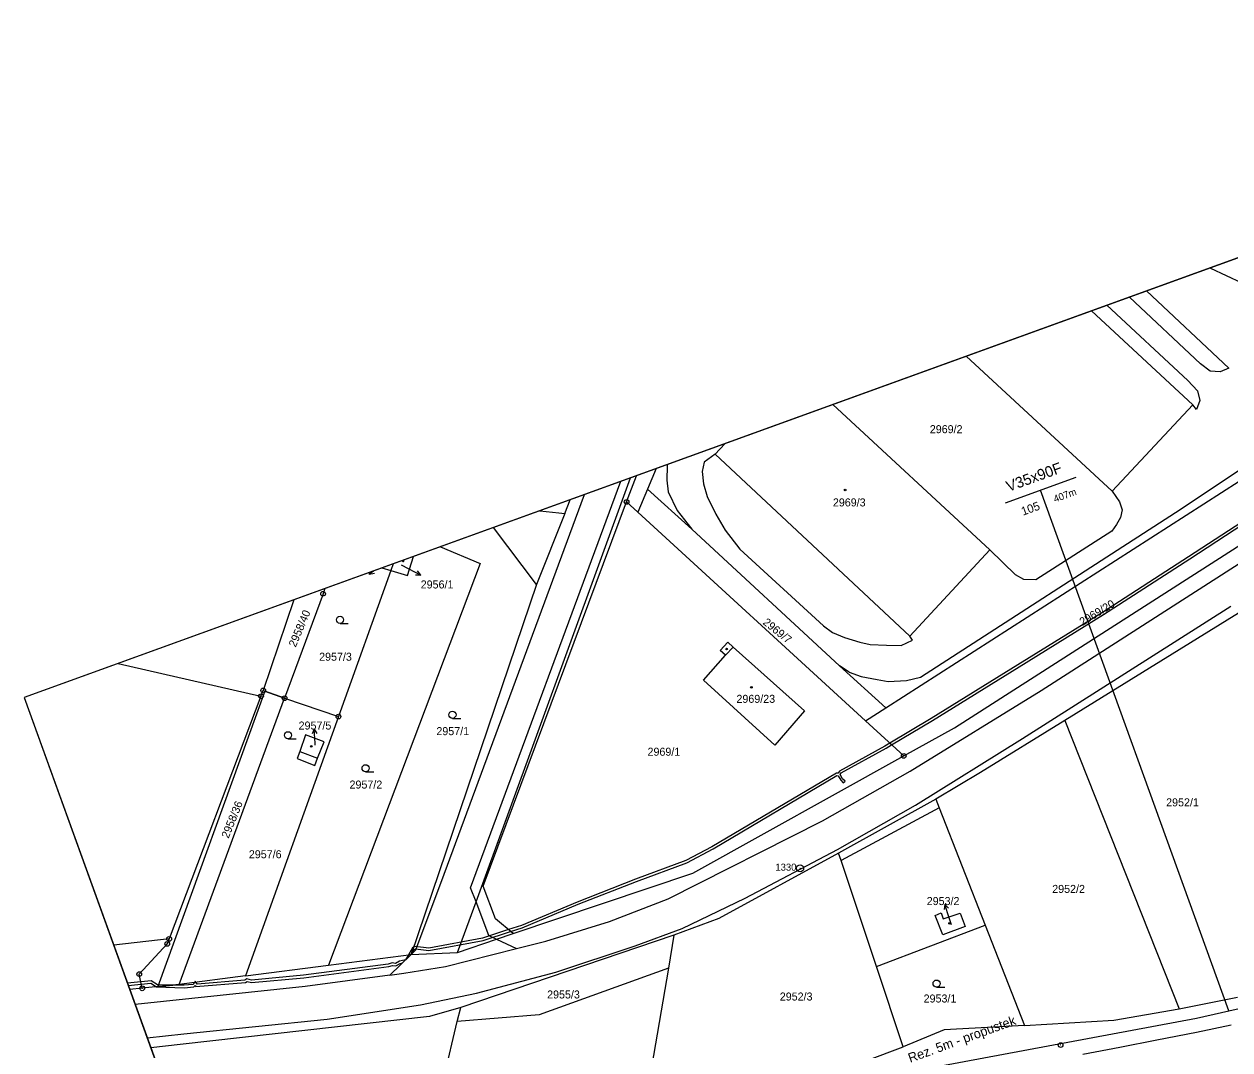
# Model space of a CAD drawing. Extents: x -620552 to -620056, y -1123312 to -1122890.
# Drawn here: x -620552.1 to -620295.9, y -1123107.4 to -1122889.6 of the extents above; entities that cross this region are included whole.
import ezdxf

# ---------------------------------------------------------------- set-up
doc = ezdxf.new("R2010")
doc.units = 0
for name, color, linetype in [('HranDP', 7, 'Continuous'), ('Hranice parcel', 7, 'Continuous'), ('Parcelní čísla', 7, 'Continuous'), ('Pop  PČ popisy', 7, 'Continuous'), ('Rámečky', 7, 'Continuous'), ('Rámečky-tisk', 7, 'Continuous'), ('Vnitřní kresba', 7, 'Continuous'), ('Vrstva 1', 7, 'Continuous'), ('Vrstva 3', 7, 'Continuous'), ('Vrstva 33', 7, 'Continuous'), ('Vrstva 7', 7, 'Continuous'), ('Věcná břemena k části', 7, 'Continuous'), ('Značky bodu BP', 7, 'Continuous'), ('Značky budov', 7, 'Continuous'), ('Značky kultur', 7, 'Continuous')]:
    doc.layers.add(name, color=color, linetype=linetype)

msp = doc.modelspace()

# ---------------------------------------------------------------- linework, layer by layer
at = {"layer": 'HranDP'}
msp.add_line((-620306.69, -1123098.69), (-620294.3, -1123096.22), dxfattribs=at)
for points in [[(-620339.56, -1123102.2), (-620320.55, -1123101.1), (-620306.69, -1123098.69)], [(-620339.56, -1123102.2), (-620356.6, -1123103.13), (-620365.33, -1123106.73)], [(-620420.55, -1123121.3), (-620381.33, -1123112.8), (-620365.33, -1123106.73)]]:
    msp.add_lwpolyline(points, dxfattribs=at)
at = {"layer": 'Hranice parcel'}
for p, q in [((-620369, -1123034.76), (-620282.4, -1122979.23)), ((-620419.67, -1122988.35), (-620421.73, -1122993.23)), ((-620437.23, -1122993.52), (-620436.06, -1122990.58)), ((-620421.73, -1122993.23), (-620424.09, -1122991.06)), ((-620437.23, -1122993.52), (-620443.21, -1123008.56)), ((-620373.35, -1123037.54), (-620421.73, -1122993.23)), ((-620470.61, -1123006.71), (-620469.37, -1123002.64)), ((-620474.2, -1123005.64), (-620485.32, -1123036.63)), ((-620473.68, -1123004.21), (-620474.2, -1123005.64)), ((-620474.2, -1123005.64), (-620470.61, -1123006.71)), ((-620443.21, -1123008.56), (-620469.88, -1123087.14)), ((-620488.59, -1123010.56), (-620496.76, -1123032.74)), ((-620488.18, -1123009.46), (-620488.59, -1123010.56)), ((-620289.02, -1123011.5), (-620330.98, -1123037.45)), ((-620494.8, -1123011.85), (-620501.3, -1123031.09)), ((-620501.77, -1123032.32), (-620501.3, -1123031.09)), ((-620501.77, -1123032.32), (-620521.28, -1123083.84)), ((-620519.15, -1123093.5), (-620496.76, -1123032.74)), ((-620496.76, -1123032.74), (-620485.32, -1123036.63)), ((-620485.32, -1123036.63), (-620505.08, -1123091.68)), ((-620373.35, -1123037.54), (-620369, -1123034.76)), ((-620365.22, -1123044.99), (-620373.35, -1123037.54)), ((-620330.98, -1123037.45), (-620306.69, -1123098.69)), ((-620358.43, -1123054.16), (-620379.05, -1123065.63)), ((-620414.05, -1123083.02), (-620459.28, -1123098.4)), ((-620414.05, -1123083.02), (-620415.21, -1123090.05)), ((-620487.43, -1123089.4), (-620469.88, -1123087.14)), ((-620505.08, -1123091.68), (-620487.43, -1123089.4)), ((-620415.21, -1123090.05), (-620420.55, -1123121.3)), ((-620519.15, -1123093.5), (-620527.01, -1123094.34)), ((-620505.08, -1123091.68), (-620519.15, -1123093.5)), ((-620460.08, -1123101.38), (-620459.28, -1123098.4)), ((-620306.69, -1123098.69), (-620294.3, -1123096.22)), ((-620466.92, -1123130.28), (-620460.08, -1123101.38))]:
    msp.add_line(p, q, dxfattribs=at)
for points in [[(-620325.34, -1122950.49), (-620303.81, -1122970.47), (-620320.91, -1122988.8), (-620351.92, -1122960.11)], [(-620380.28, -1122970.38), (-620346.89, -1123001.2)], [(-620346.89, -1123001.2), (-620363.9, -1123019.53), (-620405.31, -1122980.94), (-620403.21, -1122978.69)], [(-620424.09, -1122991.06), (-620422.01, -1122985.49)], [(-620417.81, -1122983.97), (-620419.67, -1122988.35)], [(-620419.67, -1122988.35), (-620410.26, -1122996.87), (-620378.87, -1123025.88), (-620369, -1123034.76)], [(-620448.18, -1123082.73), (-620451.92, -1123079.58), (-620454.55, -1123072.66), (-620424.09, -1122991.06)], [(-620442.54, -1122992.93), (-620438.47, -1122993.38), (-620437.23, -1122993.52)], [(-620365.22, -1123044.99), (-620354.45, -1123039), (-620287.33, -1122996.04)], [(-620443.21, -1123008.56), (-620452.34, -1122996.48)], [(-620463.61, -1123000.56), (-620455.23, -1123004.12), (-620487.43, -1123089.4)], [(-620476.09, -1123005.08), (-620474.2, -1123005.64)], [(-620402.6, -1123020.87), (-620401.48, -1123021.87), (-620386.27, -1123035.43), (-620392.63, -1123042.68), (-620407.79, -1123028.9), (-620403.06, -1123023.63), (-620404.19, -1123022.62), (-620402.6, -1123020.87)], [(-620532.11, -1123025.36), (-620501.77, -1123032.32)], [(-620501.3, -1123031.09), (-620500.99, -1123031.21), (-620496.76, -1123032.74)], [(-620330.98, -1123037.45), (-620348.88, -1123048.53), (-620358.43, -1123054.16)], [(-620488.38, -1123042.02), (-620492.3, -1123040.51), (-620493.55, -1123044.02), (-620494.11, -1123045.54), (-620490.35, -1123047.05), (-620489.79, -1123045.46), (-620488.38, -1123042.02)], [(-620448.18, -1123082.73), (-620410.01, -1123069.89), (-620365.22, -1123044.99)], [(-620358.43, -1123054.16), (-620357.7, -1123056.02), (-620347.91, -1123080.94), (-620339.56, -1123102.2)], [(-620379.05, -1123065.63), (-620404.47, -1123079.48), (-620414.05, -1123083.02)], [(-620365.33, -1123106.73), (-620371.02, -1123089.67), (-620378.51, -1123067.23), (-620379.05, -1123065.63)], [(-620353.21, -1123078.36), (-620352.17, -1123081.18), (-620356.92, -1123082.98), (-620358.53, -1123078.86), (-620357.25, -1123078.34), (-620356.83, -1123079.58), (-620353.21, -1123078.36)], [(-620469.88, -1123087.14), (-620460.03, -1123086.72), (-620451.71, -1123083.91), (-620448.18, -1123082.73)], [(-620521.28, -1123083.84), (-620533.07, -1123085.14)], [(-620527.01, -1123094.34), (-620527.63, -1123091.32), (-620521.69, -1123084.92), (-620521.28, -1123083.84)], [(-620469.88, -1123087.14), (-620474.39, -1123091.54), (-620492.38, -1123093.94), (-620528.51, -1123097.74)], [(-620415.21, -1123090.05), (-620442.66, -1123100), (-620460.08, -1123101.38)], [(-620527.01, -1123094.34), (-620529.64, -1123094.62)], [(-620459.28, -1123098.4), (-620466, -1123100.3), (-620518.97, -1123106.26), (-620525.17, -1123106.96)], [(-620339.56, -1123102.2), (-620320.55, -1123101.1), (-620306.69, -1123098.69)], [(-620339.56, -1123102.2), (-620356.6, -1123103.13), (-620365.33, -1123106.73)], [(-620420.55, -1123121.3), (-620381.33, -1123112.8), (-620365.33, -1123106.73)]]:
    msp.add_lwpolyline(points, dxfattribs=at)
at = {"layer": 'Pop  PČ popisy'}
for p, q in [((-620477.9, -1123005.73), (-620478.77, -1123006.39)), ((-620478.77, -1123006.39), (-620478.56, -1123005.97)), ((-620478.77, -1123006.39), (-620477.67, -1123006.18)), ((-620472, -1123004.4), (-620470.49, -1123005.2)), ((-620470.49, -1123005.2), (-620467.84, -1123006.61)), ((-620467.84, -1123006.61), (-620468.49, -1123005.7)), ((-620467.84, -1123006.61), (-620468.96, -1123006.58)), ((-620490.44, -1123039.28), (-620490.89, -1123040.31)), ((-620490.28, -1123042.28), (-620490.44, -1123039.28)), ((-620490.44, -1123039.28), (-620489.89, -1123040.26)), ((-620490.26, -1123042.74), (-620490.28, -1123042.28)), ((-620356.5, -1123076.52), (-620356.66, -1123077.62)), ((-620355.57, -1123079.37), (-620356.5, -1123076.52)), ((-620356.5, -1123076.52), (-620355.71, -1123077.31)), ((-620355.09, -1123080.85), (-620355.57, -1123079.37))]:
    msp.add_line(p, q, dxfattribs=at)
at = {"layer": 'Rámečky'}
msp.add_line((-620157.19, -1122889.6), (-620552.1, -1123032.6), dxfattribs=at)
msp.add_lwpolyline([(-620552.1, -1123032.6), (-620450.98, -1123311.85), (-620056.07, -1123168.86)], dxfattribs=at)
at = {"layer": 'Rámečky-tisk'}
msp.add_line((-620552.1, -1123032.6), (-620450.98, -1123311.85), dxfattribs=at)
msp.add_lwpolyline([(-620450.98, -1123311.85), (-620056.07, -1123168.86), (-620157.19, -1122889.6), (-620552.1, -1123032.6)], dxfattribs=at)
at = {"layer": 'Vnitřní kresba'}
for p, q in [((-620300.09, -1122941.34), (-620300.01, -1122941.39)), ((-620300.01, -1122941.39), (-620293.37, -1122944.55)), ((-620313.63, -1122946.25), (-620296.17, -1122962.67)), ((-620322.07, -1122949.31), (-620304.85, -1122965.25)), ((-620302.2, -1122961.76), (-620317.24, -1122947.56)), ((-620300.14, -1122963.26), (-620302.2, -1122961.76)), ((-620296.17, -1122962.67), (-620297.96, -1122963.41)), ((-620304.85, -1122965.25), (-620302.84, -1122967.46)), ((-620297.96, -1122963.41), (-620300.14, -1122963.26)), ((-620302.84, -1122967.46), (-620302.33, -1122969.49)), ((-620303.05, -1122971.44), (-620303.81, -1122970.47)), ((-620302.33, -1122969.49), (-620303.05, -1122971.44)), ((-620415.51, -1122983.37), (-620415.58, -1122986.43)), ((-620415.44, -1122983.11), (-620415.51, -1122983.37)), ((-620407.63, -1122982.63), (-620408.01, -1122984.62)), ((-620405.31, -1122980.94), (-620407.63, -1122982.63)), ((-620307.51, -1122993.27), (-620292.44, -1122983.33)), ((-620456.08, -1123075.99), (-620423.24, -1122985.94)), ((-620408.01, -1122984.62), (-620407.79, -1122987.2)), ((-620457.23, -1123072.97), (-620425.29, -1122986.68)), ((-620415.58, -1122986.43), (-620415.3, -1122988.94)), ((-620407.79, -1122987.2), (-620406.97, -1122989.87)), ((-620462.82, -1123070.13), (-620433.05, -1122989.49)), ((-620415.3, -1122988.94), (-620413.36, -1122992.91)), ((-620406.97, -1122989.87), (-620405.11, -1122993.68)), ((-620320.91, -1122988.8), (-620319.39, -1122991.07)), ((-620319.39, -1122991.07), (-620318.78, -1122992.75)), ((-620413.36, -1122992.91), (-620410.26, -1122996.87)), ((-620361.67, -1123028.28), (-620307.51, -1122993.27)), ((-620318.78, -1122992.75), (-620319.15, -1122994.37)), ((-620405.11, -1122993.68), (-620403.13, -1122997.02)), ((-620319.98, -1122995.84), (-620320.99, -1122997.25)), ((-620319.15, -1122994.37), (-620319.98, -1122995.84)), ((-620403.13, -1122997.02), (-620400.01, -1123001.09)), ((-620320.99, -1122997.25), (-620337.13, -1123007.62)), ((-620400.01, -1123001.09), (-620382.25, -1123017.34)), ((-620341.49, -1123006.57), (-620346.89, -1123001.2)), ((-620336.04, -1123031.13), (-620285.65, -1122998.79)), ((-620339.7, -1123007.56), (-620341.49, -1123006.57)), ((-620337.13, -1123007.62), (-620339.7, -1123007.56)), ((-620339.98, -1123041.29), (-620295.72, -1123013.16)), ((-620382.25, -1123017.34), (-620380.35, -1123018.75)), ((-620380.35, -1123018.75), (-620377.77, -1123019.86)), ((-620377.77, -1123019.86), (-620374.53, -1123020.83)), ((-620374.53, -1123020.83), (-620372.37, -1123021.35)), ((-620372.37, -1123021.35), (-620368.87, -1123021.48)), ((-620368.87, -1123021.48), (-620365.77, -1123021.56)), ((-620365.77, -1123021.56), (-620363.32, -1123020.4)), ((-620363.32, -1123020.4), (-620363.9, -1123019.53)), ((-620403.06, -1123023.63), (-620401.48, -1123021.87)), ((-620376.83, -1123027.23), (-620378.87, -1123025.88)), ((-620376.83, -1123027.23), (-620374.25, -1123028.1)), ((-620374.25, -1123028.1), (-620370.88, -1123028.79)), ((-620370.88, -1123028.79), (-620368.56, -1123029.21)), ((-620368.56, -1123029.21), (-620364.63, -1123029)), ((-620364.63, -1123029), (-620361.67, -1123028.28)), ((-620363.85, -1123048.22), (-620336.04, -1123031.13)), ((-620362.71, -1123055.46), (-620339.98, -1123041.29)), ((-620493.55, -1123044.02), (-620489.79, -1123045.46)), ((-620382.46, -1123058.76), (-620363.85, -1123048.22)), ((-620379.28, -1123064.86), (-620362.71, -1123055.46)), ((-620357.7, -1123056.02), (-620378.51, -1123067.23)), ((-620415.29, -1123075.34), (-620382.46, -1123058.76)), ((-620398.9, -1123075.2), (-620379.28, -1123064.86)), ((-620468.85, -1123086.16), (-620462.82, -1123070.13)), ((-620456.08, -1123075.99), (-620457.23, -1123072.97)), ((-620427.73, -1123080.16), (-620415.29, -1123075.34)), ((-620412.3, -1123081.62), (-620398.9, -1123075.2)), ((-620460.03, -1123086.72), (-620456.08, -1123075.99)), ((-620453.39, -1123083.13), (-620456.08, -1123075.99)), ((-620441.26, -1123084.35), (-620427.73, -1123080.16)), ((-620453.39, -1123083.13), (-620451.71, -1123083.91)), ((-620422.27, -1123085.3), (-620412.3, -1123081.62)), ((-620371.02, -1123089.67), (-620347.91, -1123080.94)), ((-620451.71, -1123083.91), (-620447.48, -1123085.9)), ((-620447.48, -1123085.9), (-620441.26, -1123084.35)), ((-620439.16, -1123090.89), (-620422.27, -1123085.3)), ((-620469.88, -1123087.14), (-620468.85, -1123086.16)), ((-620462.59, -1123089.69), (-620447.48, -1123085.9)), ((-620471.42, -1123091.14), (-620462.59, -1123089.69)), ((-620455.99, -1123095.39), (-620439.16, -1123090.89)), ((-620474.39, -1123091.54), (-620471.42, -1123091.14)), ((-620467.87, -1123097.88), (-620455.99, -1123095.39)), ((-620487.74, -1123100.91), (-620467.87, -1123097.88)), ((-620518.16, -1123103.97), (-620487.74, -1123100.91)), ((-620525.94, -1123104.83), (-620518.16, -1123103.97))]:
    msp.add_line(p, q, dxfattribs=at)
at = {"layer": 'Vrstva 1'}
for points in [[(-620490.54, -1123135.38), (-620469.22, -1123131.24), (-620467.69, -1123132.26), (-620387.47, -1123116.43), (-620372.49, -1123113.59), (-620361.88, -1123111.62), (-620302.99, -1123100.7), (-620292.4, -1123098.24)], [(-620295.67, -1123102.19), (-620303.02, -1123103.7), (-620311.43, -1123105.36), (-620319.33, -1123106.87), (-620327.2, -1123108.39)]]:
    msp.add_lwpolyline(points, dxfattribs=at)
at = {"layer": 'Vrstva 33'}
for p, q in [((-620328.63, -1122985.87), (-620343.67, -1122991.32)), ((-620296.13, -1123099.11), (-620336.15, -1122988.59))]:
    msp.add_line(p, q, dxfattribs=at)
at = {"layer": 'Vrstva 7'}
msp.add_line((-620331.84, -1123106.38), (-620331.94, -1123106.4), dxfattribs=at)
msp.add_circle((-620331.89, -1123106.39), 0.5, dxfattribs=at)
at = {"layer": 'Věcná břemena k části'}
msp.add_line((-620530.14, -1123093.23), (-620529.96, -1123093.72), dxfattribs=at)
for points in [[(-620359.12, -1123037.46), (-620340.69, -1123026.08), (-620322.75, -1123014.93), (-620304.43, -1123003.11), (-620287.42, -1122992.06), (-620285.83, -1122990.94), (-620285.6, -1122990.17), (-620287.7, -1122991.64), (-620304.71, -1123002.69), (-620323.01, -1123014.51), (-620340.95, -1123025.66), (-620359.38, -1123037.04), (-620368.18, -1123042.28), (-620367.79, -1123042.63)], [(-620519.15, -1123093.5), (-620496.76, -1123032.74), (-620500.99, -1123031.21), (-620523.67, -1123093.98)], [(-620449.19, -1123081.88), (-620448.73, -1123082.26), (-620446.29, -1123081.47), (-620434.42, -1123076.48), (-620422.01, -1123071.64), (-620411.29, -1123067.69), (-620405.72, -1123064.74), (-620379.41, -1123049.16), (-620379.14, -1123049.19), (-620378.61, -1123050.13), (-620378.05, -1123050.72), (-620377.69, -1123050.38), (-620378.21, -1123049.83), (-620378.69, -1123048.95), (-620378.5, -1123048.59), (-620368.96, -1123043.33), (-620367.79, -1123042.63), (-620368.18, -1123042.28), (-620369.2, -1123042.89), (-620378.86, -1123048.23), (-620379.12, -1123048.68), (-620379.53, -1123048.64), (-620405.96, -1123064.3), (-620411.49, -1123067.23), (-620422.19, -1123071.18), (-620434.6, -1123076.02), (-620446.45, -1123080.99)], [(-620448.73, -1123082.26), (-620449.19, -1123081.88), (-620454.74, -1123083.69), (-620466.13, -1123085.82), (-620468.99, -1123085.45), (-620469.37, -1123085.62), (-620469.88, -1123087.14), (-620469.21, -1123086.1), (-620468.91, -1123085.97), (-620466.11, -1123086.32), (-620454.6, -1123084.17)], [(-620469.57, -1123085.72), (-620470.44, -1123087.21), (-620469.88, -1123087.14), (-620469.37, -1123085.62)], [(-620471.73, -1123088.95), (-620471.08, -1123088.32), (-620472.35, -1123088.56), (-620473.2, -1123089.06), (-620473.9, -1123088.94), (-620474.74, -1123089.2), (-620492.73, -1123091.58), (-620503.76, -1123092.62), (-620504.76, -1123092.35), (-620505.19, -1123092.63), (-620515.35, -1123093.45), (-620515.6, -1123093.04), (-620515.93, -1123093.08), (-620516.27, -1123093.53), (-620518.09, -1123093.7), (-620520.51, -1123093.64), (-620523.94, -1123094.01), (-620518.07, -1123094.2), (-620516.01, -1123094.01), (-620515.77, -1123093.71), (-620515.61, -1123093.97), (-620505.03, -1123093.11), (-620504.68, -1123092.89), (-620503.8, -1123093.12), (-620492.67, -1123092.08), (-620474.64, -1123089.7), (-620473.86, -1123089.46), (-620473.1, -1123089.58), (-620472.17, -1123089.04)], [(-620469.88, -1123087.14), (-620470.44, -1123087.21), (-620471.08, -1123088.32)], [(-620515.73, -1123092.83), (-620515.93, -1123093.08), (-620515.6, -1123093.04)]]:
    msp.add_lwpolyline(points, close=True, dxfattribs=at)
msp.add_lwpolyline([(-620529.96, -1123093.72), (-620525.21, -1123093.27), (-620523.94, -1123094.01), (-620520.51, -1123093.64), (-620523.79, -1123093.57), (-620525.09, -1123092.75), (-620530.14, -1123093.23)], dxfattribs=at)
at = {"layer": 'Značky bodu BP'}
for centre, radius in [((-620424.09, -1122991.06), 0.5), ((-620424.09, -1122991.06), 0.0303), ((-620488.59, -1123010.56), 0.5), ((-620488.59, -1123010.56), 0.0303), ((-620501.77, -1123032.32), 0.5), ((-620501.3, -1123031.09), 0.5), ((-620501.3, -1123031.09), 0.0303), ((-620501.77, -1123032.32), 0.0303), ((-620496.76, -1123032.74), 0.5), ((-620496.76, -1123032.74), 0.0303), ((-620485.32, -1123036.63), 0.5), ((-620485.32, -1123036.63), 0.0303), ((-620365.22, -1123044.99), 0.5), ((-620365.22, -1123044.99), 0.0303), ((-620387.23, -1123068.86), 0.75), ((-620387.23, -1123068.86), 0.03), ((-620521.69, -1123084.92), 0.5), ((-620521.28, -1123083.84), 0.5), ((-620521.69, -1123084.92), 0.0303), ((-620521.28, -1123083.84), 0.0303), ((-620527.63, -1123091.32), 0.5), ((-620527.63, -1123091.32), 0.0303), ((-620527.01, -1123094.34), 0.5), ((-620527.01, -1123094.34), 0.0303)]:
    msp.add_circle(centre, radius, dxfattribs=at)
at = {"layer": 'Značky budov'}
msp.add_line((-620471.46, -1123003.4), (-620471.71, -1123003.49), dxfattribs=at)
for centre in [(-620377.67, -1122988.52), (-620402.85, -1123022.3), (-620397.57, -1123030.41), (-620491.08, -1123042.96), (-620355.49, -1123080.54)]:
    msp.add_circle(centre, 0.175, dxfattribs=at)
msp.add_arc((-620471.55, -1123003.55), 0.175, 160.6156, 59.196, dxfattribs=at)
at = {"layer": 'Značky kultur'}
for p, q in [((-620484.98, -1123016.84), (-620483.23, -1123016.84)), ((-620461.09, -1123037.01), (-620459.34, -1123037.01)), ((-620496.04, -1123041.34), (-620494.29, -1123041.34)), ((-620479.55, -1123048.35), (-620477.8, -1123048.35)), ((-620358.24, -1123094.08), (-620356.49, -1123094.08))]:
    msp.add_line(p, q, dxfattribs=at)
for centre in [(-620484.98, -1123016.09), (-620461.09, -1123036.26), (-620496.04, -1123040.59), (-620479.55, -1123047.6), (-620358.24, -1123093.33)]:
    msp.add_circle(centre, 0.75, dxfattribs=at)

# ---------------------------------------------------------------- texts
at = {"layer": 'Parcelní čísla'}
for s, p in [('2969/2', (-620359.68, -1122976.46)), ('2969/3', (-620380.27, -1122992.01)), ('2956/1', (-620467.84, -1123009.43)), ('2957/3', (-620489.42, -1123024.78)), ('2969/23', (-620400.76, -1123033.72)), ('2957/5', (-620493.78, -1123039.39)), ('2957/1', (-620464.51, -1123040.58)), ('2969/1', (-620419.65, -1123044.95)), ('2957/2', (-620482.96, -1123051.92)), ('2952/1', (-620309.47, -1123055.7)), ('2957/6', (-620504.35, -1123066.72)), ('2952/2', (-620333.67, -1123074.08)), ('2953/2', (-620360.33, -1123076.66)), ('2955/3', (-620440.98, -1123096.49)), ('2952/3', (-620391.55, -1123096.93)), ('2953/1', (-620360.99, -1123097.35))]:
    msp.add_text(s, height=1.7, dxfattribs=at).set_placement(p)
for s, rotation, p in [('2958/40', 67, (-620494.41, -1123022.03)), ('2969/20', 31, (-620327.24, -1123017.4)), ('2969/7', 321, (-620395.29, -1123016.88)), ('2958/36', 68, (-620508.68, -1123062.62))]:
    msp.add_text(s, height=1.7, rotation=rotation, dxfattribs=at).set_placement(p)
at = {"layer": 'Vrstva 3'}
msp.add_text('Rez. 5m - propustek', height=2, rotation=19.9058, dxfattribs=at).set_placement((-620363.85, -1123110.16))
at = {"layer": 'Vrstva 33'}
for s, height, p in [('V35x90F', 2.3, (-620342.95, -1122988.93)), ('407m', 1.5, (-620333.08, -1122991.2)), ('105', 1.8, (-620339.88, -1122993.99))]:
    msp.add_text(s, height=height, rotation=19.9058, dxfattribs=at).set_placement(p)
at = {"layer": 'Značky bodu BP'}
msp.add_text('1330', height=1.5, dxfattribs=at).set_placement((-620392.48, -1123069.36))

doc.saveas('drawing.dxf')
